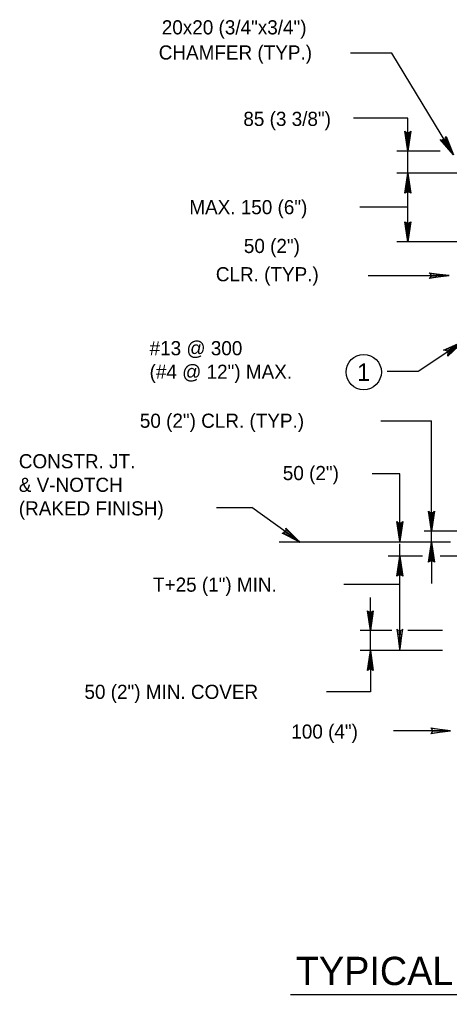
# Model space of a CAD drawing. Extents: x 652000 to 652262, y 303155 to 303399.
# Drawn here: x 651999.6 to 652090.8, y 303155 to 303361.9 of the extents above; entities that cross this region are included whole.
import ezdxf

# ---------------------------------------------------------------- set-up
doc = ezdxf.new("R2010")
doc.units = 0
doc.layers.add('2', color=7, linetype='Continuous')

msp = doc.modelspace()

# ---------------------------------------------------------------- linework, layer by layer
at = {"layer": '2'}
for p, q in [((652078.56, 303354.7), (652069.81, 303354.7)), ((652091.69, 303333.14), (652078.56, 303354.7)), ((652082, 303340.96), (652070.48, 303340.96)), ((652082, 303333.92), (652082, 303340.96)), ((652088.88, 303333.92), (652079.66, 303333.92)), ((652082, 303329.24), (652082, 303333.77)), ((652092.94, 303329.24), (652079.66, 303329.24)), ((652082, 303314.71), (652082, 303329.24)), ((652082, 303322.05), (652071.82, 303322.05)), ((652092.94, 303314.71), (652079.66, 303314.71)), ((652073.57, 303307.52), (652090.75, 303307.52)), ((652093.88, 303293.61), (652084.19, 303287.21)), ((652084.19, 303287.21), (652077.63, 303287.21)), ((652076.23, 303276.74), (652087, 303276.74)), ((652087, 303253.3), (652087, 303276.74)), ((652080.29, 303265.49), (652074.38, 303265.49)), ((652080.29, 303251.11), (652080.29, 303265.49)), ((652041.35, 303258.31), (652048.9, 303258.31)), ((652058.89, 303251.13), (652048.9, 303258.31)), ((652087, 303250.96), (652087, 303256.74)), ((652093.02, 303253.3), (652085.44, 303253.3)), ((652091.07, 303250.96), (652054.69, 303250.96)), ((652080.29, 303247.21), (652080.29, 303250.64)), ((652087, 303250.96), (652087, 303242.21)), ((652085.13, 303247.99), (652077.79, 303247.99)), ((652080.29, 303227.99), (652080.29, 303247.99)), ((652126.22, 303247.99), (652088.88, 303247.99)), ((652080.15, 303241.98), (652068.43, 303241.98)), ((652074.04, 303232.21), (652074.04, 303239.24)), ((652078.57, 303232.21), (652071.85, 303232.21)), ((652074.04, 303227.99), (652074.04, 303232.21)), ((652089.35, 303232.21), (652082, 303232.21)), ((652089.35, 303227.99), (652071.85, 303227.99)), ((652074.04, 303227.99), (652074.04, 303219.24)), ((652074.04, 303219.24), (652064.73, 303219.24)), ((652091.07, 303210.96), (652078.97, 303210.96)), ((652057.09, 303155.02), (652243.28, 303155.02))]:
    msp.add_line(p, q, dxfattribs=at)
for points in [[(652082.47, 303337.99), (652082.16, 303337.83), (652082, 303333.92), (652082.47, 303337.99), (652082.63, 303338.14), (652082, 303333.92), (652081.85, 303337.83), (652081.54, 303337.99), (652082, 303333.92), (652081.38, 303338.14), (652081.54, 303337.99)], [(652082.47, 303337.99), (652082.16, 303337.83), (652082, 303333.92), (652082.47, 303337.99), (652082.63, 303338.14), (652082, 303333.92), (652081.85, 303337.83), (652081.54, 303337.99), (652082, 303333.92), (652081.38, 303338.14), (652081.54, 303337.99)], [(652089.97, 303336.89), (652089.82, 303336.58), (652091.69, 303333.14), (652089.97, 303336.89), (652090.13, 303337.05), (652091.69, 303333.14), (652089.5, 303336.42), (652089.19, 303336.27), (652091.69, 303333.14), (652088.88, 303336.42), (652089.19, 303336.27)], [(652081.54, 303325.17), (652081.85, 303325.33), (652082, 303329.24), (652081.54, 303325.17), (652081.38, 303325.02), (652082, 303329.24), (652082.16, 303325.33), (652082.47, 303325.17), (652082, 303329.24), (652082.63, 303325.02), (652082.47, 303325.17)], [(652081.54, 303325.17), (652081.85, 303325.33), (652082, 303329.24), (652081.54, 303325.17), (652081.38, 303325.02), (652082, 303329.24), (652082.16, 303325.33), (652082.47, 303325.17), (652082, 303329.24), (652082.63, 303325.02), (652082.47, 303325.17)], [(652082.47, 303318.77), (652082.16, 303318.61), (652082, 303314.71), (652082.47, 303318.77), (652082.63, 303318.92), (652082, 303314.71), (652081.85, 303318.61), (652081.54, 303318.77), (652082, 303314.71), (652081.38, 303318.92), (652081.54, 303318.77)], [(652082.47, 303318.77), (652082.16, 303318.61), (652082, 303314.71), (652082.47, 303318.77), (652082.63, 303318.92), (652082, 303314.71), (652081.85, 303318.61), (652081.54, 303318.77), (652082, 303314.71), (652081.38, 303318.92), (652081.54, 303318.77)], [(652086.69, 303307.99), (652086.85, 303307.67), (652090.75, 303307.52), (652086.69, 303307.99), (652086.54, 303308.14), (652090.75, 303307.52), (652086.85, 303307.36), (652086.69, 303307.05), (652090.75, 303307.52), (652086.54, 303306.89), (652086.69, 303307.05)], [(652086.69, 303307.99), (652086.85, 303307.67), (652090.75, 303307.52), (652086.69, 303307.99), (652086.54, 303308.14), (652090.75, 303307.52), (652086.85, 303307.36), (652086.69, 303307.05), (652090.75, 303307.52), (652086.54, 303306.89), (652086.69, 303307.05)], [(652089.94, 303291.74), (652090.32, 303291.55), (652093.88, 303293.61), (652089.94, 303291.74), (652089.57, 303291.74), (652093.88, 303293.61), (652090.5, 303291.17), (652090.5, 303290.8), (652093.88, 303293.61), (652090.5, 303290.42), (652090.5, 303290.8)], [(652087.47, 303257.36), (652087.16, 303257.21), (652087, 303253.3), (652087.47, 303257.36), (652087.63, 303257.52), (652087, 303253.3), (652086.85, 303257.21), (652086.54, 303257.36), (652087, 303253.3), (652086.38, 303257.52), (652086.54, 303257.36)], [(652087.47, 303257.36), (652087.16, 303257.21), (652087, 303253.3), (652087.47, 303257.36), (652087.63, 303257.52), (652087, 303253.3), (652086.85, 303257.21), (652086.54, 303257.36), (652087, 303253.3), (652086.38, 303257.52), (652086.54, 303257.36)], [(652056.13, 303253.67), (652056.02, 303253.34), (652059.09, 303250.99), (652056.13, 303253.67), (652056.08, 303253.98), (652059.09, 303250.99), (652055.89, 303253.16), (652055.61, 303252.95), (652059.09, 303250.99), (652055.3, 303252.9), (652055.61, 303252.95)], [(652080.75, 303255.17), (652080.44, 303255.02), (652080.29, 303251.11), (652080.75, 303255.17), (652080.91, 303255.33), (652080.29, 303251.11), (652080.13, 303255.02), (652079.82, 303255.17), (652080.29, 303251.11), (652079.66, 303255.33), (652079.82, 303255.17)], [(652080.75, 303255.17), (652080.44, 303255.02), (652080.29, 303251.11), (652080.75, 303255.17), (652080.91, 303255.33), (652080.29, 303251.11), (652080.13, 303255.02), (652079.82, 303255.17), (652080.29, 303251.11), (652079.66, 303255.33), (652079.82, 303255.17)], [(652086.54, 303246.89), (652086.85, 303247.05), (652087, 303250.96), (652086.54, 303246.89), (652086.38, 303246.74), (652087, 303250.96), (652087.16, 303247.05), (652087.47, 303246.89), (652087, 303250.96), (652087.63, 303246.74), (652087.47, 303246.89)], [(652079.82, 303243.92), (652080.13, 303244.08), (652080.29, 303247.99), (652079.82, 303243.92), (652079.66, 303243.77), (652080.29, 303247.99), (652080.44, 303244.08), (652080.75, 303243.92), (652080.29, 303247.99), (652080.91, 303243.77), (652080.75, 303243.92)], [(652074.5, 303236.27), (652074.19, 303236.11), (652074.04, 303232.21), (652074.5, 303236.27), (652074.66, 303236.42), (652074.04, 303232.21), (652073.88, 303236.11), (652073.57, 303236.27), (652074.04, 303232.21), (652073.41, 303236.42), (652073.57, 303236.27)], [(652079.82, 303232.36), (652080.13, 303232.21), (652080.29, 303228.3), (652079.82, 303232.36), (652079.66, 303232.52), (652080.29, 303228.3), (652080.44, 303232.21), (652080.75, 303232.36), (652080.29, 303228.3), (652080.91, 303232.52), (652080.75, 303232.36)], [(652073.57, 303223.92), (652073.88, 303224.08), (652074.04, 303227.99), (652073.57, 303223.92), (652073.41, 303223.77), (652074.04, 303227.99), (652074.19, 303224.08), (652074.5, 303223.92), (652074.04, 303227.99), (652074.66, 303223.77), (652074.5, 303223.92)], [(652087, 303211.42), (652087.16, 303211.11), (652091.07, 303210.96), (652087, 303211.42), (652086.85, 303211.58), (652091.07, 303210.96), (652087.16, 303210.8), (652087, 303210.49), (652091.07, 303210.96), (652086.85, 303210.33), (652087, 303210.49)]]:
    msp.add_lwpolyline(points, dxfattribs=at)
msp.add_circle((652072.62, 303287.06), 3.75, dxfattribs=at)

# ---------------------------------------------------------------- texts
for s, height, p in [('20x20 (3/4"x3/4")', 3, (652029.76, 303358.7)), ('CHAMFER (TYP.)', 3, (652029.11, 303353.36)), ('85 (3 3/8")', 3, (652047.07, 303339.28)), ('MAX. 150 (6")', 3, (652035.6, 303320.55)), ('50 (2")', 3, (652047.18, 303312.32)), ('CLR. (TYP.)', 3, (652041.23, 303306.32)), ('#13 @ 300 ', 3, (652027.17, 303290.63)), ('(#4 @ 12") MAX.', 3, (652027.17, 303285.63)), ('1', 3.75, (652071.22, 303285.17)), ('50 (2") CLR. (TYP.)', 3, (652025.1, 303275.24)), ('CONSTR. JT.', 3, (651999.41, 303266.65)), ('50 (2")', 3, (652055.45, 303264.14)), ('& V-NOTCH', 3, (651999.41, 303261.65)), ('(RAKED FINISH)', 3, (651999.41, 303256.65)), ('T+25 (1") MIN.', 3, (652027.9, 303240.47)), ('50 (2") MIN. COVER', 3, (652013.34, 303217.73)), ('100 (4")', 3, (652057.25, 303209.3)), ('TYPICAL CONCRETE BARRIER DETAIL', 6, (652058.22, 303157.02))]:
    msp.add_text(s, height=height, dxfattribs=at).set_placement(p)

doc.saveas('drawing.dxf')
